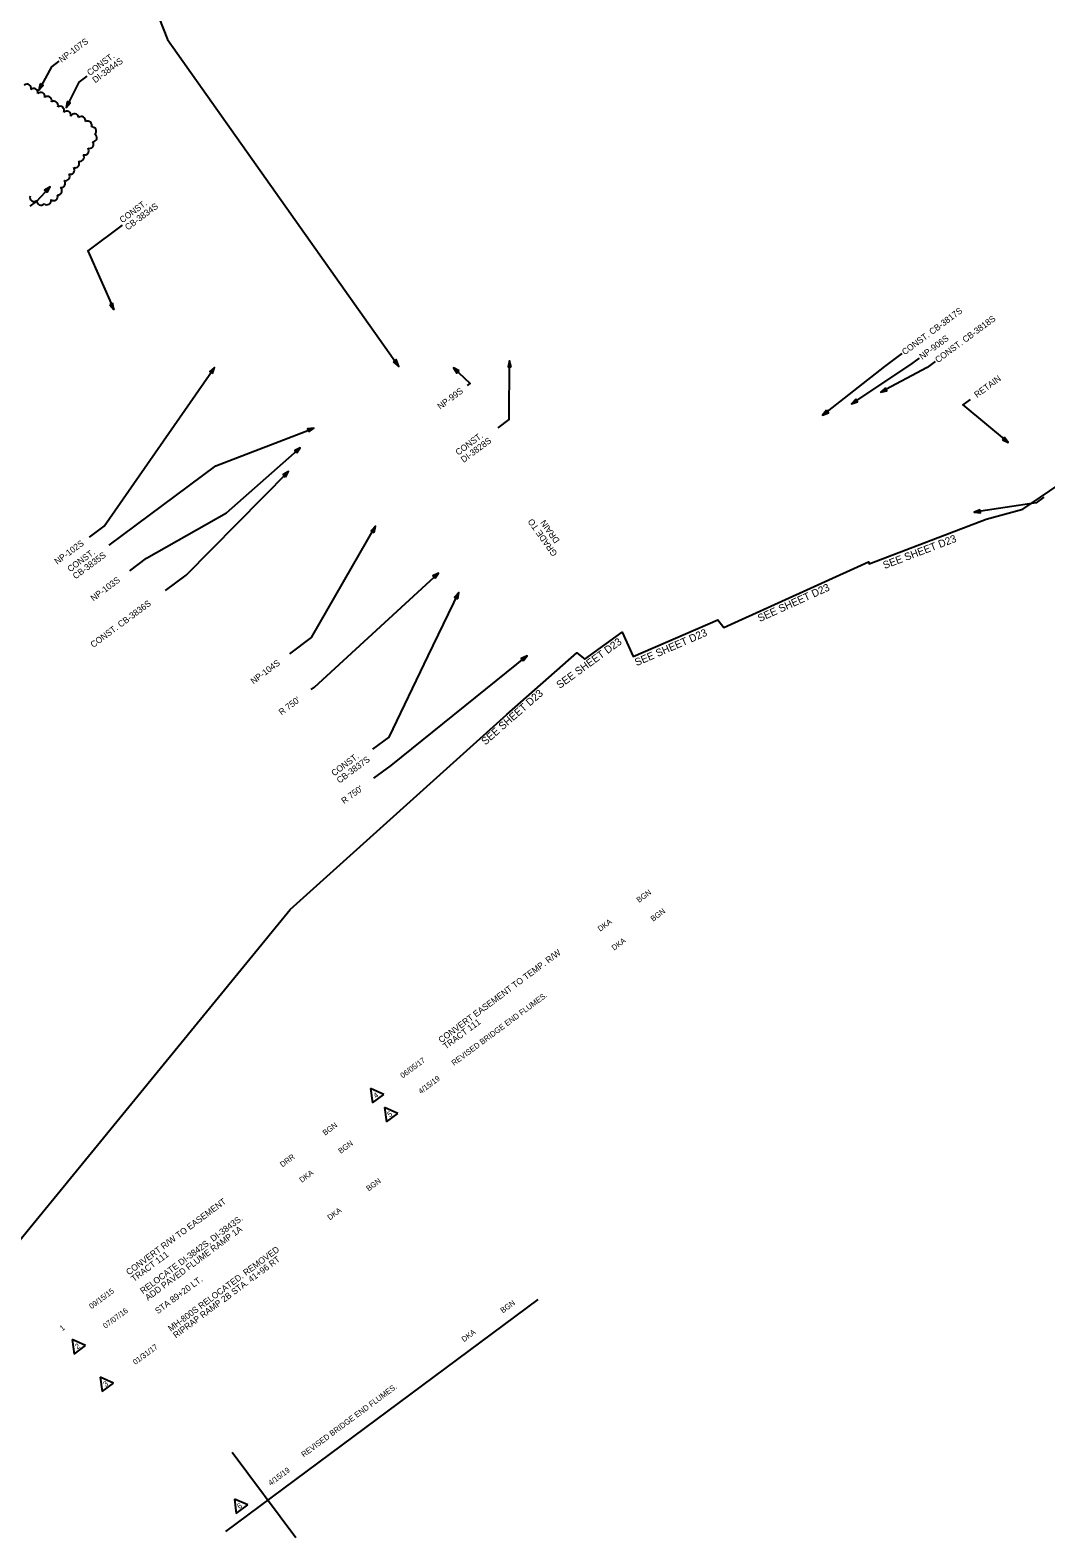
# Model space of a CAD drawing. Extents: x 1610466 to 1612467, y 1092226 to 1094137.
# Drawn here: x 1610924 to 1611735, y 1092226 to 1093429 of the extents above; entities that cross this region are included whole.
import ezdxf

# ---------------------------------------------------------------- set-up
doc = ezdxf.new("R2010")
doc.units = 0
for name, color, linetype in [('Default', 7, 'Continuous'), ('Plan_Clip', 7, 'Continuous'), ('RD_SHT_MatchLine', 7, 'Continuous'), ('RD_SHT_TX', 7, 'Continuous'), ('RD_TX_Drainage', 7, 'Continuous')]:
    doc.layers.add(name, color=color, linetype=linetype)

msp = doc.modelspace()

# ---------------------------------------------------------------- linework, layer by layer
at = {"layer": 'Default'}
msp.add_lwpolyline([(1610924, 1093288.5), (1610928.9, 1093292.2), (1610939.8, 1093303.9)], dxfattribs=at)
msp.add_lwpolyline([(1610937.5, 1093299.5), (1610939.8, 1093303.9), (1610935.5, 1093301.3)], close=True, dxfattribs=at)
at = {"layer": 'Plan_Clip'}
msp.add_lwpolyline([(1610846.9, 1093501.7), (1610834.8, 1093427.6), (1610833.3, 1093421.7), (1610813.8, 1093421.2), (1610761.6, 1093355.2), (1610787.3, 1093333.5), (1610710.6, 1093240.4), (1610594.6, 1093177.6), (1610466.3, 1093048.1), (1610903.7, 1092448.8), (1611131.4, 1092727.3), (1611304.4, 1092882.9), (1611360.4, 1092932), (1611366.6, 1092927), (1611396.5, 1092948.7), (1611405.3, 1092929.1), (1611472.9, 1092958.4), (1611477.7, 1092952.2), (1611593.2, 1093004.6), (1611593.8, 1093003.2), (1611687.1, 1093038.8), (1611716.3, 1093046.8), (1612140.1, 1093334.6)], dxfattribs=at)
at = {"layer": 'RD_SHT_TX'}
for p, q in [((1611206.3, 1092579.5), (1611195.7, 1092584.3)), ((1611195.7, 1092584.3), (1611197.2, 1092572.8)), ((1611197.2, 1092572.8), (1611206.3, 1092579.5)), ((1611217.5, 1092564.5), (1611206.9, 1092569.3)), ((1611206.9, 1092569.3), (1611208.4, 1092557.7)), ((1611208.4, 1092557.7), (1611217.5, 1092564.5)), ((1611329.2, 1092416), (1611079.9, 1092230.7)), ((1610968.2, 1092379.2), (1610957.6, 1092384)), ((1610957.6, 1092384), (1610959.1, 1092372.4)), ((1610959.1, 1092372.4), (1610968.2, 1092379.2)), ((1610990.5, 1092349.2), (1610979.9, 1092354)), ((1610979.9, 1092354), (1610981.4, 1092342.4)), ((1610981.4, 1092342.4), (1610990.5, 1092349.2)), ((1611135.9, 1092225.7), (1611085.3, 1092293.9)), ((1611097.6, 1092252), (1611087, 1092256.7)), ((1611087, 1092256.7), (1611088.5, 1092245.2)), ((1611088.5, 1092245.2), (1611097.6, 1092252))]:
    msp.add_line(p, q, dxfattribs=at)
at = {"layer": 'RD_TX_Drainage'}
for points in [[(1611008.5, 1093555.4), (1610987.3, 1093539.6), (1611033.7, 1093421.5), (1611218.3, 1093160.6)], [(1610946.8, 1093404.3), (1610940.9, 1093399.9), (1610930.8, 1093381.3)], [(1610969.2, 1093392.3), (1610962.7, 1093387.5), (1610952.6, 1093367.3)], [(1610997.5, 1093273.4), (1610970, 1093252.9), (1610990.7, 1093206)], [(1611297.6, 1093111.7), (1611306.3, 1093118.2), (1611306.7, 1093165.2)], [(1611619.8, 1093170.9), (1611605.9, 1093160.6), (1611556.5, 1093121.7)], [(1611633.7, 1093167.3), (1611627.8, 1093163), (1611579.7, 1093130.9)], [(1611646.3, 1093164.6), (1611639.9, 1093159.8), (1611602.9, 1093140.1)], [(1610971.4, 1093024.5), (1610983.1, 1093033.3), (1611071.2, 1093159.8)], [(1611273, 1093145.4), (1611275.3, 1093147.1), (1611261.9, 1093159.6)], [(1611674.3, 1093134.4), (1611668.4, 1093130), (1611704.6, 1093099.9)], [(1610986.9, 1093018), (1611072.2, 1093081.4), (1611150.3, 1093111.5)], [(1611003.5, 1092997.6), (1611016.9, 1093007.6), (1611080.8, 1093043.9), (1611139.6, 1093095.8)], [(1611032, 1092981.8), (1611048.4, 1092994), (1611130.2, 1093076.8)], [(1611733.2, 1093056.4), (1611727, 1093051.7), (1611677.6, 1093044.3)], [(1611131.2, 1092931.4), (1611148.6, 1092944.4), (1611199.7, 1093033.1)], [(1611148.3, 1092902.9), (1611150.8, 1092904.7), (1611250, 1092995.8)], [(1611197.6, 1092855.1), (1611210.6, 1092864.8), (1611241.7, 1092929.6), (1611266.1, 1092980.2)], [(1611198.4, 1092832), (1611212, 1092842.2), (1611320.6, 1092929.6)]]:
    msp.add_lwpolyline(points, dxfattribs=at)
for points in [[(1610932, 1093386.2), (1610930.8, 1093381.3), (1610934.2, 1093384.9)], [(1610953.6, 1093372.2), (1610952.6, 1093367.3), (1610955.9, 1093371)], [(1610987.6, 1093209.9), (1610990.7, 1093206), (1610990, 1093210.9)], [(1611213.7, 1093164.4), (1611218.3, 1093160.6), (1611216.2, 1093166.2)], [(1611308, 1093160.4), (1611306.7, 1093165.2), (1611305.4, 1093160.4)], [(1611069.5, 1093155.1), (1611071.2, 1093159.8), (1611067.4, 1093156.6)], [(1611266.3, 1093157.3), (1611261.9, 1093159.6), (1611264.6, 1093155.4)], [(1611606.6, 1093143.5), (1611602.9, 1093140.1), (1611607.8, 1093141.2)], [(1611559.5, 1093125.7), (1611556.5, 1093121.7), (1611561.1, 1093123.6)], [(1611583, 1093134.6), (1611579.7, 1093130.9), (1611584.4, 1093132.5)], [(1611146.3, 1093108.6), (1611150.3, 1093111.5), (1611145.4, 1093111)], [(1611700.1, 1093102), (1611704.6, 1093099.9), (1611701.7, 1093104)], [(1611136.9, 1093091.7), (1611139.6, 1093095.8), (1611135.1, 1093093.6)], [(1611127.7, 1093072.4), (1611130.2, 1093076.8), (1611125.8, 1093074.3)], [(1611682.2, 1093046.3), (1611677.6, 1093044.3), (1611682.6, 1093043.8)], [(1611198.5, 1093028.2), (1611199.7, 1093033.1), (1611196.2, 1093029.5)], [(1611247.3, 1092991.6), (1611250, 1092995.8), (1611245.5, 1092993.5)], [(1611265.2, 1092975.3), (1611266.1, 1092980.2), (1611262.8, 1092976.4)], [(1611317.6, 1092925.6), (1611320.6, 1092929.6), (1611316, 1092927.6)]]:
    msp.add_lwpolyline(points, close=True, dxfattribs=at)
for centre, start, end in [((1610921.4, 1093382.6), 344.7232, 129.7232), ((1610926.8, 1093379.2), 347.3973, 132.3973), ((1610932.4, 1093376.1), 349.0343, 134.0343), ((1610937.8, 1093372.9), 343.9752, 128.9752), ((1610942.9, 1093369.1), 338.4383, 123.4383), ((1610947.7, 1093365), 335.7723, 120.7723), ((1610953.1, 1093361.2), 347.9562, 132.9562), ((1610959.3, 1093359), 8.2884, 153.2884), ((1610964.8, 1093356.9), 345.5924, 130.5924), ((1610969.8, 1093353.2), 335.6458, 120.6458), ((1610973.3, 1093348.5), 313.3045, 98.3045), ((1610973.8, 1093343.3), 272.4155, 57.4155), ((1610963.6, 1093327.7), 250.8687, 35.8687), ((1610967.4, 1093332.8), 250.8687, 35.8687), ((1610971.2, 1093338), 250.8687, 35.8687), ((1610956, 1093317.4), 250.8687, 35.8687), ((1610959.8, 1093322.6), 250.8687, 35.8687), ((1610948.7, 1093306.8), 259.7486, 44.7486), ((1610952.2, 1093312.3), 250.8687, 35.8687), ((1610927.1, 1093295.7), 166.352, 311.352), ((1610932.6, 1093292.8), 173.2788, 318.2788), ((1610937.4, 1093293.1), 226.9348, 11.9348), ((1610942.7, 1093296.4), 233.7006, 18.7006), ((1610946, 1093300.9), 267.0101, 52.0101)]:
    msp.add_arc(centre, 3.35, start, end, dxfattribs=at)

# ---------------------------------------------------------------- texts
at = {"layer": 'RD_SHT_MatchLine'}
for rotation, p in [(20.8649, (1611606, 1092998.9)), (24.4049, (1611506.3, 1092956.6)), (36.0552, (1611346.7, 1092903.2)), (23.4637, (1611408.1, 1092921.4)), (41.2017, (1611287.3, 1092858.1))]:
    msp.add_text('SEE SHEET D23', height=6, rotation=rotation, dxfattribs=at).set_placement(p)
at = {"layer": 'RD_SHT_TX'}
for s, height, rotation, p in [('BGN', 4.4, 36.6272, (1611410, 1092732.4)), ('BGN', 4.4, 36.6272, (1611421.2, 1092717.4)), ('DKA', 4.4, 36.6272, (1611379, 1092709.4)), ('DKA', 4.4, 36.6272, (1611390.1, 1092694.3)), ('CONVERT EASEMENT TO TEMP. R/W ', 5, 36.6272, (1611252.1, 1092620.4)), ('REVISED BRIDGE END FLUMES.', 4.5, 36.6272, (1611262.3, 1092602.3)), ('TRACT 111', 5, 36.6272, (1611255.8, 1092615.4)), ('06/05/17', 4.4, 36.6272, (1611221.4, 1092592.3)), ('4/15/19', 4.4, 36.6272, (1611235.8, 1092579.7)), ('4', 4.4, 36.6272, (1611199.9, 1092576.2)), ('5', 4.4, 36.6272, (1611211, 1092561.2)), ('BGN', 4.4, 36.6256, (1611159.4, 1092546.6)), ('BGN', 4.4, 36.6272, (1611171.9, 1092532.1)), ('DRR', 4.4, 36.6256, (1611125.4, 1092521.3)), ('DKA', 4.4, 36.6272, (1611140.8, 1092509)), ('BGN', 4.4, 36.6272, (1611194.2, 1092502.1)), ('CONVERT R/W TO EASEMENT', 5, 36.6272, (1611002.8, 1092435.1)), ('DKA', 4.4, 36.6272, (1611163.2, 1092479)), ('RELOCATE DI-3842S, DI-3843S.', 5, 36.6272, (1611014, 1092420.1)), ('ADD PAVED FLUME RAMP 1A', 5, 36.6272, (1611018, 1092414.8)), ('TRACT 111', 5, 36.6272, (1611006.8, 1092429.8)), ('MH-800S RELOCATED. REMOVED', 5, 36.6272, (1611036.3, 1092390.1)), ('RIPRAP RAMP 2B STA. 41+96 RT', 5, 36.6272, (1611040.3, 1092384.8)), ('STA 89+20 LT.', 5, 36.6272, (1611025.9, 1092404.1)), ('09/15/15', 4.4, 36.6256, (1610973, 1092408.1)), ('BGN', 4.4, 36.6272, (1611301.3, 1092404.8)), ('07/07/16', 4.4, 36.6272, (1610984.1, 1092392.5)), ('1', 4.4, 36.6256, (1610949.5, 1092390.6)), ('DKA', 4.4, 36.6272, (1611270.3, 1092381.8)), ('2', 4.4, 36.6272, (1610961.7, 1092375.9)), ('01/31/17', 4.4, 36.6272, (1611007.9, 1092363.6)), ('3', 4.4, 36.6272, (1610984.1, 1092345.9)), ('REVISED BRIDGE END FLUMES.', 4.5, 36.6272, (1611142.4, 1092289.8)), ('4/15/19', 4.4, 36.6272, (1611116, 1092267.1)), ('6', 4.4, 36.6272, (1611091.1, 1092248.5))]:
    msp.add_text(s, height=height, rotation=rotation, dxfattribs=at).set_placement(p)
at = {"layer": 'RD_TX_Drainage'}
for s, rotation, p in [('NP-107S', 36.6256, (1610949.1, 1093402.9)), ('CONST.', 36.6256, (1610971.6, 1093392.4)), ('DI-3844S', 36.6256, (1610975.9, 1093386.6)), ('CONST.', 36.6256, (1610997.6, 1093274.9)), ('CB-3834S', 36.6256, (1611001.9, 1093269.1)), ('CONST. CB-3817S', 36.6256, (1611622.1, 1093169.5)), ('CONST. CB-3818S', 36.6256, (1611648.6, 1093163.2)), ('NP-906S', 36.6256, (1611636, 1093165.9)), ('RETAIN', 36.6256, (1611679.8, 1093135.4)), ('NP-99S', 36.6256, (1611251.3, 1093126.1)), ('CONST.', 36.6256, (1611265.7, 1093089.4)), ('DI-3828S', 36.6256, (1611270, 1093083.6)), ('GRADE TO', 125.4175, (1611345.1, 1093011.3)), ('DRAIN', 125.4175, (1611346.9, 1093021.8)), ('NP-102S', 36.6256, (1610945.6, 1093002.3)), ('CONST.', 36.6256, (1610955.9, 1092996.3)), ('CB-3835S', 36.6256, (1610960.2, 1092990.6)), ('NP-103S', 36.6256, (1610974.5, 1092973)), ('CONST. CB-3836S', 36.6256, (1610974.4, 1092935.9)), ('NP-104S', 36.6256, (1611102.2, 1092906.8)), ("R 750'", 36.6256, (1611124.6, 1092882.1)), ('CONST.', 36.6256, (1611166.6, 1092833.4)), ('CB-3837S', 36.6256, (1611170.9, 1092827.6)), ("R 750'", 36.6256, (1611174.6, 1092811.2))]:
    msp.add_text(s, height=5, rotation=rotation, dxfattribs=at).set_placement(p)

doc.saveas('drawing.dxf')
